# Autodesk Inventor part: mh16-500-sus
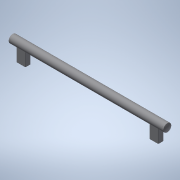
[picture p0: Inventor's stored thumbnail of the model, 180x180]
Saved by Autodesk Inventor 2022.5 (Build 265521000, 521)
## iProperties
Created: 2016-12
Part Number: mh16-500-sus
Material: 一般
Document SubType Name: Modeling
Designer: imaocorp
Density: 1 g/cm^3
Appearance: 既定
Author: imaocorp
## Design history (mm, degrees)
node "mh16-500-sus.x_t1"
node "mh16-500-sus"
node "Base1"
